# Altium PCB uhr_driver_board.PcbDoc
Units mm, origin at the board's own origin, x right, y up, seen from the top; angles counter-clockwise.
Board outline 152.4 x 101.6 mm, 2 copper layers (Top Layer, Bottom Layer); 130 components, 204 nets, 564 pads, 16 vias.
Unrouted connection lines stored in the file: 255.
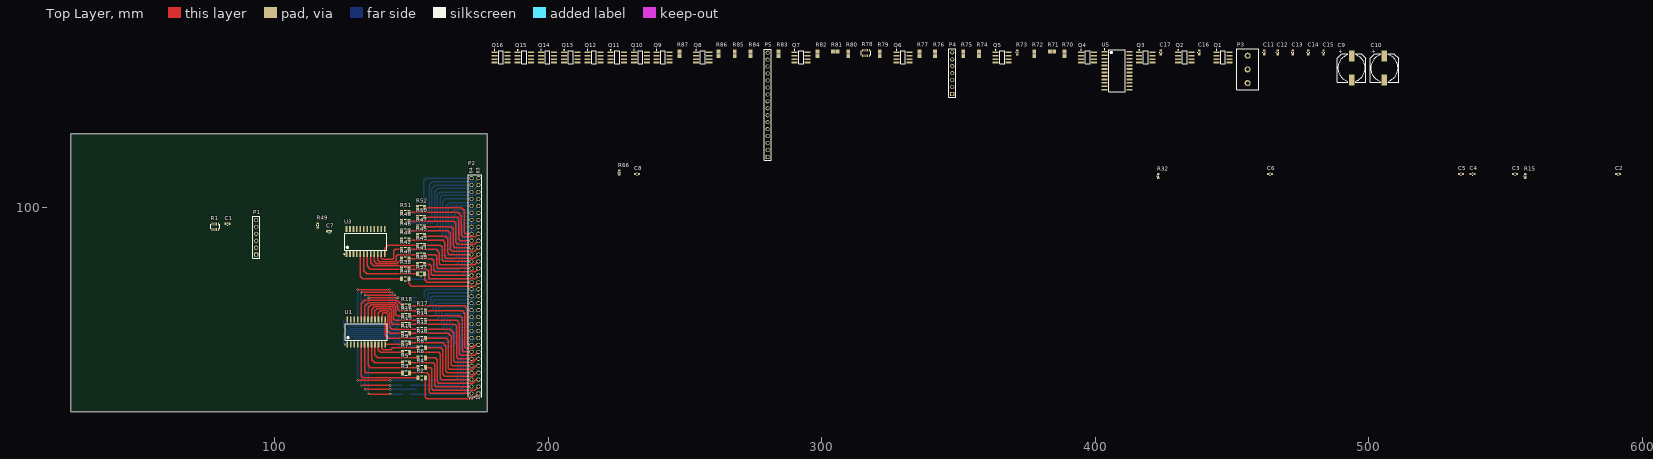
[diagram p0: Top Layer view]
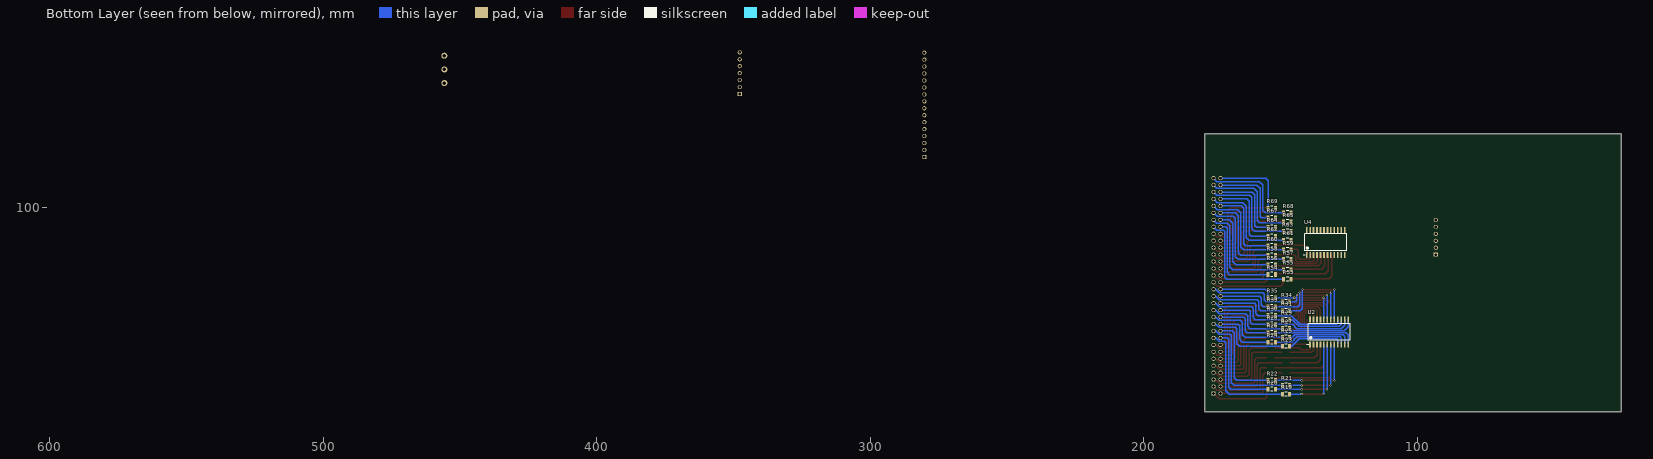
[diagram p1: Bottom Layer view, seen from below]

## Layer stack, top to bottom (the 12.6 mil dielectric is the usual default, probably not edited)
Top Layer: signal copper 0.0356
Dielectric: dielectric 0.32, FR-4, Dk 4.8
Bottom Layer: signal copper 0.0356

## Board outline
25.4,25.4 177.8,25.4 177.8,127 25.4,127

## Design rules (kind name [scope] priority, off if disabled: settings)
Clearance [All] p1: gap=0.125
DiffPairsRouting [All] p1: maxlimit=10 minlimit=0.125 mostfreqgap=0.15 maxuncoupledlength=12.7
FabricationTestPointUsage FabricationTestPointUsage_1 [All] p1: valid=0 allowmultiple=FALSE
FabricationTestpoint FabricationTestpoint_1 [All] p1: side=3 testpointundercomponent=TRUE minsize=1.016 maxsize=2.54 preferedsize=1.524 minholesize=0 maxholesize=1.016 preferedholesize=0.813 testpointgrid=0.025 allowsidetop=TRUE allowsidebottom=TRUE usegrid=TRUE gridtolerance=0
HoleSize [All] p1: absolutevalues=TRUE maxlimit=6 minlimit=0.2 maxpercent=80.000 minpercent=20.000
HoleSize FabricationTestpoint [All] p2 off: absolutevalues=TRUE maxlimit=2.54 minlimit=0.025 maxpercent=80.000 minpercent=20.000
HoleSize FabricationTestPointUsage [All] p3 off: absolutevalues=TRUE maxlimit=2.54 minlimit=0.025 maxpercent=80.000 minpercent=20.000
PlaneClearance [All] p1: clearance=0.5
PlaneConnect [All] p1: planeconnectstyle=Relief reliefexpansion=0.4 reliefentries=4 reliefconductorwidth=0.15 reliefairgap=0.15
PolygonConnect [All] p1: connectstyle=Relief reliefconductorwidth=0.15 reliefentries=4 polygonreliefangle="90 Angle" airgapwidth=0.254
RoutingCorners [All] p1: cornerstyle=45-Degree minsetback=1.25 maxsetback=1.25
RoutingVias [All] p1: holewidth=0.3 width=0.6 viastyle="Through Hole" minholewidth=0.2 minwidth=0.45 maxholewidth=0.45 maxwidth=0.75
SolderMaskExpansion [All] p1: expansion=0.075
Width [All] p1: maxlimit=10 minlimit=0.125 preferedwidth=0.15
21 further rules are at their usual default settings.

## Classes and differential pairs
component class main_driver_column: C1 C2 C3 C4 C5 C6 C7 C8 P1 P2 R1 R2 R3 R4 R5 R6 R7 R8 R9 R10 R11 R12 R13 R14 R15 R16 R17 R19 R20 R21 R22 R23 R24 R25 R26 R27 R28 R29 R30 R31 R32 R33 R34 R35 R36 R37 R38 R39 R40 R41 R42 R43 R44 R45 R46 R47 R48 R49 R50 R51 R52 R53 R54 R55 R56 R57 R58 R59 R60 R61 R62 R63 R64 R65 R66 R67 R68 R69 U1 U2 U3 U4
component class main_driver_row: C9 C10 C11 C12 C13 C14 C15 C16 C17 P3 P4 P5 Q1 Q2 Q3 Q4 Q5 Q6 Q7 Q8 Q9 Q10 Q11 Q12 Q13 Q14 Q15 Q16 R70 R71 R72 R73 R74 R75 R76 R77 R78 R79 R80 R81 R82 R83 R84 R85 R86 R87 U5
net class LED_COL[1..64]: LED_COL1 LED_COL2 LED_COL3 LED_COL4 LED_COL5 LED_COL6 LED_COL7 LED_COL8 LED_COL9 LED_COL10 LED_COL11 LED_COL12 LED_COL13 LED_COL14 LED_COL15 LED_COL16 LED_COL17 LED_COL18 LED_COL19 LED_COL20 LED_COL21 LED_COL22 LED_COL23 LED_COL24 LED_COL25 LED_COL26 LED_COL27 LED_COL28 LED_COL29 LED_COL30 LED_COL31 LED_COL32 LED_COL33 LED_COL34 LED_COL35 LED_COL36 LED_COL37 LED_COL38 LED_COL39 LED_COL40 LED_COL41 LED_COL42 LED_COL43 LED_COL44 LED_COL45 LED_COL46 LED_COL47 LED_COL48 LED_COL49 LED_COL50 LED_COL51 LED_COL52 LED_COL53 LED_COL54 LED_COL55 LED_COL56 LED_COL57 LED_COL58 LED_COL59 LED_COL60 LED_COL61 LED_COL62 LED_COL63 LED_COL64

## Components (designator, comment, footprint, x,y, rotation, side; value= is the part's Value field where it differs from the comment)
C1 "2U2F_0603" C0603 82.749,94 r0 top
C2 "10PF_0603" C0603 591.249,112.25 r0 top
C3 "10PF_0603" C0603 553.499,112.25 r0 top
C4 "10PF_0603" C0603 537.999,112.25 r0 top
C5 "10PF_0603" C0603 533.749,112.25 r0 top
C6 "2U2F_0603" C0603 463.999,112.25 r0 top
C7 "2U2F_0603" C0603 119.95,91.25 r0 top
C8 "2U2F_0603" C0603 232.5,112.25 r0 top
C9 "470UF_V_CAPEIA_G" CAPAE_G 493.749,151 r0 top
C10 "470UF_V_CAPEIA_G" CAPAE_G 505.749,151 r0 top
C11 "2U2F_0603" C0603 461.749,156.75 r90 top
C12 "2U2F_0603" C0603 466.749,156.75 r90 top
C13 "2U2F_0603" C0603 472.249,156.75 r90 top
C14 "2U2F_0603" C0603 477.999,156.75 r90 top
C15 "2U2F_0603" C0603 483.499,156.75 r90 top
C16 "2U2F_0603" C0603 437.999,156.75 r90 top
C17 "100NF_0603" C0603 423.999,156.75 r90 top
P1 "Header 6" HDR1X6_1MM 93.25,82.75 r90 top
P2 "Header 32X2" HDR2X32_1MM 174.5,32 r90 top
P3 "Header 3" Header_3_Screw_5mm 455.749,150.5 r90 top
P4 "Header 7" HDR1X7_1MM 347.749,141.5 r90 top
P5 "Header 16" HDR1X16_1MM 280.249,118.5 r90 top
Q1 "NTMS10P02" SOIC-8 446.749,153 r0 top
Q2 "NTMS10P02" SOIC-8 432.749,153 r0 top
Q3 "NTMS10P02" SOIC-8 418.499,153 r0 top
Q4 "NTMS10P02" SOIC-8 397.249,153 r0 top
Q5 "NTMS10P02" SOIC-8 365.999,153 r0 top
Q6 "NTMS10P02" SOIC-8 329.749,153 r0 top
Q7 "NTMS10P02" SOIC-8 292.499,153 r0 top
Q8 "NTMS10P02" SOIC-8 256.499,153 r0 top
Q9 "NTMS10P02" SOIC-8 242,153 r0 top
Q10 "NTMS10P02" SOIC-8 233.75,153 r0 top
Q11 "NTMS10P02" SOIC-8 225.25,153 r0 top
Q12 "NTMS10P02" SOIC-8 216.75,153 r0 top
Q13 "NTMS10P02" SOIC-8 208.25,153 r0 top
Q14 "NTMS10P02" SOIC-8 199.75,153 r0 top
Q15 "NTMS10P02" SOIC-8 191.25,153 r0 top
Q16 "NTMS10P02" SOIC-8 182.75,153 r0 top
R1 "Res_Array_BCN16" BCN16 78.249,93 r0 top
R2 "15R_1206" R1206 153.75,37.75 r0 top
R3 "15R_1206" R1206 148,39.5 r0 top
R4 "15R_1206" R1206 153.75,41.5 r0 top
R5 "15R_1206" R1206 148,43.25 r0 top
R6 "15R_1206" R1206 153.75,45 r0 top
R7 "15R_1206" R1206 148,47 r0 top
R8 "15R_1206" R1206 153.75,48.75 r0 top
R9 "15R_1206" R1206 148,50.5 r0 top
R10 "15R_1206" R1206 153.75,52.25 r0 top
R11 "15R_1206" R1206 148,54 r0 top
R12 "15R_1206" R1206 153.75,55.5 r0 top
R13 "15R_1206" R1206 148,57.25 r0 top
R14 "15R_1206" R1206 153.75,58.75 r0 top
R15 "680R_0603" R0603 557.249,111.5 r90 top
R16 "15R_1206" R1206 148,60.5 r0 top
R17 "15R_1206" R1206 153.75,62.25 r0 top
R18 "15R_1206" R1206 148,64 r0 top
R19 "15R_1206" R1206 148,31.75 r0 bottom
R20 "15R_1206" R1206 153.25,33.5 r0 bottom
R21 "15R_1206" R1206 148,35 r0 bottom
R22 "15R_1206" R1206 153.25,36.75 r0 bottom
R23 "15R_1206" R1206 148,49.25 r0 bottom
R24 "15R_1206" R1206 153.25,50.75 r0 bottom
R25 "15R_1206" R1206 148,52.5 r0 bottom
R26 "15R_1206" R1206 153.25,54.25 r0 bottom
R27 "15R_1206" R1206 148,55.75 r0 bottom
R28 "15R_1206" R1206 153.25,57.25 r0 bottom
R29 "15R_1206" R1206 148,59 r0 bottom
R30 "15R_1206" R1206 153.25,60.5 r0 bottom
R31 "15R_1206" R1206 148,62.25 r0 bottom
R32 "680R_0603" R0603 422.999,111.5 r90 top
R33 "15R_1206" R1206 153.25,63.75 r0 bottom
R34 "15R_1206" R1206 148,65.5 r0 bottom
R35 "15R_1206" R1206 153.25,67 r0 bottom
R36 "15R_1206" R1206 147.75,74 r0 top
R37 "15R_1206" R1206 153.5,75.75 r0 top
R38 "15R_1206" R1206 147.75,77.5 r0 top
R39 "15R_1206" R1206 153.5,79.25 r0 top
R40 "15R_1206" R1206 147.75,81.25 r0 top
R41 "15R_1206" R1206 153.5,82.75 r0 top
R42 "15R_1206" R1206 147.75,84.75 r0 top
R43 "15R_1206" R1206 153.5,86.25 r0 top
R44 "15R_1206" R1206 147.75,88.25 r0 top
R45 "15R_1206" R1206 153.5,89.75 r0 top
R46 "15R_1206" R1206 147.75,91.5 r0 top
R47 "15R_1206" R1206 153.5,93 r0 top
R48 "15R_1206" R1206 147.75,95 r0 top
R49 "680R_0603" R0603 115.699,93.5 r90 top
R50 "15R_1206" R1206 153.5,96.5 r0 top
R51 "15R_1206" R1206 147.75,98.25 r0 top
R52 "15R_1206" R1206 153.5,100 r0 top
R53 "15R_1206" R1206 147.5,73.75 r0 bottom
R54 "15R_1206" R1206 153.25,75.5 r0 bottom
R55 "15R_1206" R1206 147.5,77.25 r0 bottom
R56 "15R_1206" R1206 153.25,79 r0 bottom
R57 "15R_1206" R1206 147.5,81 r0 bottom
R58 "15R_1206" R1206 153.25,82.5 r0 bottom
R59 "15R_1206" R1206 147.5,84.5 r0 bottom
R60 "15R_1206" R1206 153.25,86 r0 bottom
R61 "15R_1206" R1206 147.5,88 r0 bottom
R62 "15R_1206" R1206 153.25,89.5 r0 bottom
R63 "15R_1206" R1206 147.5,91.25 r0 bottom
R64 "15R_1206" R1206 153.25,92.75 r0 bottom
R65 "15R_1206" R1206 147.5,94.75 r0 bottom
R66 "680R_0603" R0603 226,112.75 r90 top
R67 "15R_1206" R1206 153.25,96.25 r0 bottom
R68 "15R_1206" R1206 147.5,98 r0 bottom
R69 "15R_1206" R1206 153.25,99.75 r0 bottom
R70 "2R2_0805" R0805 388.749,156.25 r90 top
R71 "2R2_0805" R0805 384.249,157 r0 top
R72 "2R2_0805" R0805 377.749,156.25 r90 top
R73 "100R_0603" R0603 371.499,156.75 r90 top
R74 "2R2_0805" R0805 357.499,156.25 r90 top
R75 "2R2_0805" R0805 351.749,156.25 r90 top
R76 "2R2_0805" R0805 341.499,156.25 r90 top
R77 "2R2_0805" R0805 335.749,156.25 r90 top
R78 "Res_Array_BCN16" BCN16 316.249,156.5 r0 top
R79 "2R2_0805" R0805 321.249,156.25 r90 top
R80 "2R2_0805" R0805 309.749,156.25 r90 top
R81 "2R2_0805" R0805 304.999,157 r0 top
R82 "2R2_0805" R0805 298.499,156.25 r90 top
R83 "2R2_0805" R0805 284.249,156.25 r90 top
R84 "2R2_0805" R0805 273.999,156.25 r90 top
R85 "2R2_0805" R0805 268.249,156.25 r90 top
R86 "2R2_0805" R0805 262.249,156.25 r90 top
R87 "2R2_0805" R0805 248,156.25 r90 top
U1 "CAT4016" SOIC-24_W 133.5,54.5 r90 top
U2 "CAT4016" SOIC-24_W 132.25,54.5 r90 bottom
U3 "CAT4016" SOIC-24_W 133.25,87.5 r90 top
U4 "CAT4016" SOIC-24_W 133.5,87.25 r90 bottom
U5 "74HC154" SOIC-24_W 407.999,150 r0 top

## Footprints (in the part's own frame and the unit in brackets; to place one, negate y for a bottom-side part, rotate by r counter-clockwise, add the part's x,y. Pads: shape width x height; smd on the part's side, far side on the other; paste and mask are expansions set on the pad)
BCN16 [mm]
  rect 0.45x1 smd: 1(-1.2,-1) 2(-0.4,-1) 3(0.4,-1) 4(1.2,-1) 5(1.2,1) 6(0.4,1) 7(-0.4,1) 8(-1.2,1)
  silkscreen extent -1.7,-0.8 1.7,0.8, body extent -1.6,-0.8 1.6,0.8, height 0.5
C0603 [mm] "Chip Capacitor, Body 1.6x0.8mm, IPC High Density"
  rect 0.8x0.9 smd: 1(-0.7,0) 2(0.7,0)
  silkscreen extent -0.1,-0.45 0.1,0.45, body extent -0.8,-0.4 0.8,0.4, height 0.55
CAPAE_G [mm]
  rect 2x4.1 smd: 1(0,4.35) 2(0,-4.35)
  silkscreen extent -5.2,-5.2 5.2,5.2, body extent -5.15,-5.8 5.15,5.8, height 10.2
HDR1X6_1MM [mm] "Connector; Header; 6 Position"
  rect 1.5x1.5 hole 1: 1(0,0)
  round 1.5 hole 1: 2(2.54,0) 3(5.08,0) 4(7.62,0) 5(10.16,0) 6(12.7,0)
  silkscreen extent -1.27,-1.27 13.97,1.27
HDR1X7_1MM [mm] "Connector; Header; 7 Position"
  rect 1.5x1.5 hole 1: 1(0,0)
  round 1.5 hole 1: 2(2.54,0) 3(5.08,0) 4(7.62,0) 5(10.16,0) 6(12.7,0) 7(15.24,0)
  silkscreen extent -1.27,-1.27 16.51,1.27
HDR1X16_1MM [mm] "Connector; Header; 16 Position"
  rect 1.5x1.5 hole 1: 1(0,0)
  round 1.5 hole 1: 2(2.54,0) 3(5.08,0) 4(7.62,0) 5(10.16,0) 6(12.7,0) 7(15.24,0) 8(17.78,0) 9(20.32,0) 10(22.86,0) 11(25.4,0) 12(27.94,0) 13(30.48,0) 14(33.02,0) 15(35.56,0) 16(38.1,0)
  silkscreen extent -1.27,-1.27 39.37,1.27
HDR2X32_1MM [mm] "Connector; Header; 30x2 Position"
  rect 1.5x1.5 hole 1: 1(0,0)
  round 1.5 hole 1: 2(0,2.54) 3(2.54,0) 4(2.54,2.54) 5(5.08,0) 6(5.08,2.54) 7(7.62,0) 8(7.62,2.54) 9(10.16,0) 10(10.16,2.54) 11(12.7,0) 12(12.7,2.54) 13(15.24,0) 14(15.24,2.54) 15(17.78,0) 16(17.78,2.54) 17(20.32,0) 18(20.32,2.54) 19(22.86,0) 20(22.86,2.54) 21(25.4,0) 22(25.4,2.54) 23(27.94,0) 24(27.94,2.54) 25(30.48,0) 26(30.48,2.54) 27(33.02,0) 28(33.02,2.54) 29(35.56,0) 30(35.56,2.54) 31(38.1,0) 32(38.1,2.54) 33(40.64,0) 34(40.64,2.54) 35(43.18,0) 36(43.18,2.54) 37(45.72,0) 38(45.72,2.54) 39(48.26,0) 40(48.26,2.54) 41(50.8,0) 42(50.8,2.54) 43(53.34,0) 44(53.34,2.54) 45(55.88,0) 46(55.88,2.54) 47(58.42,0) 48(58.42,2.54) 49(60.96,0) 50(60.96,2.54) 51(63.5,0) 52(63.5,2.54) 53(66.04,0) 54(66.04,2.54) 55(68.58,0) 56(68.58,2.54) 57(71.12,0) 58(71.12,2.54) 59(73.66,0) 60(73.66,2.54) 61(76.2,0) 62(76.2,2.54) 63(78.74,0) 64(78.74,2.54)
  silkscreen extent -1.27,-1.27 79.9,3.81
Header_3_Screw_5mm [mm]
  round 2.2 hole 1.3: 1(-5,0) 2(0,0) 3(5,0)
  silkscreen extent -7.5,-4 7.5,4
R0603 [mm]
  rect 0.7x0.9 smd: 1(-0.751,0.008) 2(0.749,0.008)
  silkscreen extent -0.2,-0.34 0.2,0.36, body extent -0.8,-0.39 0.8,0.41, height 0.5
R0805 [mm] "Chip Resistor, Body 2.0x1.2mm, IPC Medium Density"
  rect 1.2x1.4 smd: 1(-0.9,0) 2(0.9,0)
  silkscreen extent 0,-0.6 0,0.6, body extent -1,-0.6 1,0.6, height 0.5
R1206 [mm] "Chip Resistor, Body 3.2x1.6mm, IPC High Density"
  rect 1.1x1.7 smd: 1(-1.35,0) 2(1.35,0)
  silkscreen extent -0.4,-0.75 0.4,0.75, body extent -1.6,-0.8 1.6,0.8, height 0.6
SOIC-8 [mm] "8-Pin Small Outline Integrated Circuit 1.27 mm Pitch, IPC Medium Density"
  rect 2.2x0.6 smd: 1(-2.4,3.81) 2(-2.4,2.54) 3(-2.4,1.27) 4(-2.4,0) 5(2.4,0) 6(2.4,1.27) 7(2.4,2.54) 8(2.4,3.81)
  silkscreen extent -2.52,-0.48 0.9,4.78, body extent -3,-0.52 3,4.38, height 1.63
SOIC-24_W [mm] "SOIC, 24-Leads, Body 15,30x7,47mm, Pitch 1,27mm, IPC Medium Density"
  rect 2.2x0.6 smd: 1(-4.575,6.985) 2(-4.575,5.715) 3(-4.575,4.445) 4(-4.575,3.175) 5(-4.575,1.905) 6(-4.575,0.635) 7(-4.575,-0.635) 8(-4.575,-1.905) 9(-4.575,-3.175) 10(-4.575,-4.445) 11(-4.575,-5.715) 12(-4.575,-6.985) 13(4.575,-6.985) 14(4.575,-5.715) 15(4.575,-4.445) 16(4.575,-3.175) 17(4.575,-1.905) 18(4.575,-0.635) 19(4.575,0.635) 20(4.575,1.905) 21(4.575,3.175) 22(4.575,4.445) 23(4.575,5.715) 24(4.575,6.985)
  silkscreen extent -4.7,-7.7 3.08,7.96, body extent -5.15,-7.75 5.15,7.75, height 2.65

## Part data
C1 C2 C3 C4 C5 C6 C7 C8 C11 C12 C13 C14 C15 C16 C17: library part "Cap Semi", "Capacitor (Semiconductor SIM Model)"
C9 C10: library part "Cap Pol1", "Polarized Capacitor (Radial)"
P1: "Header, 6-Pin"
P2: "Header, 32-Pin, Dual row"
P3: "Header, 3-Pin"
P4: "Header, 7-Pin"
P5: "Header, 16-Pin"
Q1 Q2 Q3 Q4 Q5 Q6 Q7 Q8 Q9 Q10 Q11 Q12 Q13 Q14 Q15 Q16: "P-Channel MOSFET SO8"
R1 R78: "Resistor"
R2 R3 R4 R5 R6 R7 R8 R9 R10 R11 R12 R13 R14 R15 R16 R17 R18 R19 R20 R21 R22 R23 R24 R25 R26 R27 R28 R29 R30 R31 R32 R33 R34 R35 R36 R37 R38 R39 R40 R41 R42 R43 R44 R45 R46 R47 R48 R49 R50 R51 R52 R53 R54 R55 R56 R57 R58 R59 R60 R61 R62 R63 R64 R65 R66 R67 R68 R69 R70 R71 R72 R73 R74 R75 R76 R77 R79 R80 R81 R82 R83 R84 R85 R86 R87: library part Res3, "Resistor"
U1 U2 U3 U4: "16channel LED driver - constant current"

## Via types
v1: diameter 0.75, hole 0.45, Top Layer to Bottom Layer, 16 vias

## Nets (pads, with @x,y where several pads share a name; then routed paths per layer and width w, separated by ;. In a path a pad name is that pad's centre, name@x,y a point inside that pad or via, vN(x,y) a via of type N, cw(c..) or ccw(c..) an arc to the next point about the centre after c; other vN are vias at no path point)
COL_BLANK: C5.2 R1.5 U1.21 U2.21 U3.21 U4.21
COL_CLK: C2.2 R1.8 U1.3 U2.3 U3.3 U4.3
COL_LATCH: C4.2 R1.6 U1.4 U2.4 U3.4 U4.4
COL_SIN: C3.2 R1.7 U1.2
GND: C1.1 C2.1 C3.1 C4.1 C5.1 C6.1 C7.1 C8.1 C9.2 C10.2 C11.1 C12.1 C13.1 C14.1 C15.1 C16.1 C17.1 P1.1 P3.3 P4.7 R15.2 R32.2 R49.2 R66.2 U1.1 U2.1 U3.1 U4.1 U5.12 U5.19
LED1: P2.1 R2.2 | length 27.6
  Top Layer w0.5: R2.2 155.1,30.65 155.75,30 172.5,30 P2.1
LED2: P2.2 R3.2 | length 28.9
  Top Layer w0.5: R3.2 155.75,39.5 156.5,38.75 156.5,32.5 157,32 P2.2@171.46,32
LED3: P2.3 R4.2 | length 27.6
  Top Layer w0.5: R4.2 157,41.5 157.5,41 157.5,33.75 158,33.25 171.437,33.25 171.441,33.254 173.214,33.254 P2.3
LED4: P2.4 R5.2 | length 30.3
  Top Layer w0.5: R5.2 158,43.25 158.5,42.75 158.5,35 158.96,34.54 P2.4@171.46,34.54
LED5: P2.5 R6.2 | length 28.4
  Top Layer w0.5: R6.2 158.75,45 159.5,44.25 159.5,36.25 159.924,35.826 172.479,35.826 173.733,37.08 P2.5
LED6: P2.6 R7.2 | length 31.3
  Top Layer w0.5: R7.2 160,47 160.5,46.5 160.5,37.75 161.17,37.08 P2.6@171.46,37.08
LED7: P2.7 R8.2 | length 29.5
  Top Layer w0.5: R8.2 160.75,48.75 161.5,48 161.5,38.982 162.116,38.366 172.479,38.366 173.733,39.62 P2.7
LED8: P2.8 R9.2 | length 32
  Top Layer w0.5: R9.2 161.5,50.5 162.5,49.5 162.5,40.25 163.13,39.62 P2.8@171.46,39.62
LED9: P2.9 R10.2 | length 30.6
  Top Layer w0.5: R10.2 162.75,52.25 163.5,51.5 163.5,41.312 163.906,40.906 172.479,40.906 173.733,42.16 P2.9
LED10: P2.10 R11.2 | length 33.2
  Top Layer w0.5: R11.2 163.5,54 164.5,53 164.5,42.5 164.84,42.16 P2.10@171.46,42.16
LED11: P2.11 R12.2 | length 30.9
  Top Layer w0.5: R12.2 164.25,55.5 165.5,54.25 165.5,44 166.054,43.446 172.479,43.446 173.733,44.7 P2.11
LED12: P2.12 R13.2 | length 33.9
  Top Layer w0.5: R13.2 165.75,57.25 166.5,56.5 166.5,45.25 167.05,44.7 P2.12@171.46,44.7
LED13: P2.13 R14.2 | length 31.8
  Top Layer w0.5: R14.2 166.5,58.75 167.5,57.75 167.5,46.5 168,46 171.441,46 ; 171.427,46 171.441,45.986 173.246,45.986 P2.13
LED14: P2.14 R16.2 | length 34.6
  Top Layer w0.5: R16.2 167.75,60.5 168.5,59.75 168.5,47.75 169.01,47.24 P2.14@171.46,47.24
LED15: P2.15 R17.2 | length 32.9
  Top Layer w0.5: R17.2 168.5,62.25 169.5,61.25 169.5,48.802 169.776,48.526 172.479,48.526 173.733,49.78 P2.15
LED16: P2.16 R18.2 | length 35.9
  Top Layer w0.5: R18.2 169.5,64 170.5,63 170.5,50.31 171.03,49.78 P2.16
LED17: P2.17 R19.2 | length 43.9
  Bottom Layer w0.5: R19.2 168.75,31.75 170,33 170,50.5 170.566,51.066 172.479,51.066 173.733,52.32 P2.17
LED18: P2.18 R20.2 | length 35.4
  Bottom Layer w0.5: R20.2 168.25,33.5 169,34.25 169,51.75 169.57,52.32 P2.18
LED19: P2.19 R21.2 | length 43.5
  Bottom Layer w0.5: R21.2 167,35 168,36 168,53.246 168.36,53.606 172.479,53.606 173.733,54.86 P2.19
LED20: P2.20 R22.2 | length 34.5
  Bottom Layer w0.5: R22.2 166,36.75 167,37.75 167,54.25 167.61,54.86 P2.20
LED21: P2.21 R23.2 | length 31.7
  Bottom Layer w0.5: R23.2 165,49.25 166,50.25 166,55.75 166.396,56.146 172.479,56.146 173.733,57.4 P2.21
LED22: P2.22 R24.2 | length 23
  Bottom Layer w0.5: R24.2 164,50.75 165,51.75 165,56.75 165.65,57.4 P2.22
LED23: P2.23 R25.2 | length 30.9
  Bottom Layer w0.5: R25.2 163,52.5 164,53.5 164,58 164.686,58.686 172.479,58.686 173.733,59.94 P2.23
LED24: P2.24 R26.2 | length 22.4
  Bottom Layer w0.5: R26.2 162.25,54.25 163,55 163,59.5 163.44,59.94 P2.24
LED25: P2.25 R27.2 | length 30.3
  Bottom Layer w0.5: R27.2 161.25,55.75 162,56.5 162,60.5 162.726,61.226 172.479,61.226 173.733,62.48 P2.25
LED26: P2.26 R28.2 | length 21.9
  Bottom Layer w0.5: R28.2 160.25,57.25 161,58 161,62 161.48,62.48 P2.26
LED27: P2.27 R29.2 | length 29.7
  Bottom Layer w0.5: R29.2 159.25,59 160,59.75 160,63.25 160.516,63.766 172.479,63.766 173.733,65.02 P2.27
LED28: P2.28 R30.2 | length 21.1
  Bottom Layer w0.5: R30.2 158.25,60.5 159,61.25 159,64.5 159.52,65.02 P2.28
LED29: P2.29 R31.2 | length 29
  Bottom Layer w0.5: R31.2 157.25,62.25 158,63 158,65.75 158.556,66.306 172.479,66.306 173.733,67.56 P2.29
LED30: P2.30 R33.2 | length 20.4
  Bottom Layer w0.5: R33.2 156.25,63.75 157,64.5 157,67 157.56,67.56 P2.30
LED31: P2.31 R34.2 | length 28.2
  Bottom Layer w0.5: R34.2 155.25,65.5 156,66.25 156,68.25 156.596,68.846 172.479,68.846 173.733,70.1 P2.31
LED32: P2.32 R35.2 | length 19.9
  Bottom Layer w0.5: R35.2 154.75,67.15 154.75,69.25 155.6,70.1 P2.32
LED33: P2.33 R36.2 | length 28.3
  Top Layer w0.5: R36.2 149,73.9 149,72.25 150,71.25 173.11,71.25 P2.33
LED34: P2.34 R37.2 | length 19.6
  Top Layer w0.5: R37.2 154.85,73.65 155.86,72.64 P2.34
LED35: P2.35 R38.2 | length 28.7
  Top Layer w0.5: R38.2 155.5,77.5 156.25,76.75 156.25,74.5 156.75,74 173.32,74 P2.35
LED36: P2.36 R39.2 | length 20.4
  Top Layer w0.5: R39.2 156.5,79.25 157.25,78.5 157.25,75.75 157.82,75.18 P2.36
LED37: P2.37 R40.2 | length 29.9
  Top Layer w0.5: R40.2 157.5,81.25 158.25,80.5 158.25,77 158.75,76.5 173.28,76.5 P2.37
LED38: P2.38 R41.2 | length 21.5
  Top Layer w0.5: R41.2 158.75,82.75 159.25,82.25 159.25,78.25 159.78,77.72 P2.38
LED39: P2.39 R42.2 | length 30.6
  Top Layer w0.5: R42.2 159,84.75 160.25,83.5 160.25,79.5 160.75,79 173.24,79 P2.39
LED40: P2.40 R43.2 | length 22.4
  Top Layer w0.5: R43.2 160.5,86.25 161.25,85.5 161.25,80.75 161.74,80.26 P2.40
LED41: P2.41 R44.2 | length 31.8
  Top Layer w0.5: R44.2 149.35,88 161.5,88 162.25,87.25 162.25,82 162.75,81.5 173.2,81.5 P2.41
LED42: P2.42 R45.2 | length 23.1
  Top Layer w0.5: R45.2 155.1,89.5 162.5,89.5 163.25,88.75 163.25,83.5 163.95,82.8 P2.42
LED43: P2.43 R46.2 | length 32.4
  Top Layer w0.5: R46.2 163.25,91.5 164.25,90.5 164.25,84.75 165,84 173.16,84 P2.43
LED44: P2.44 R47.2 | length 23.9
  Top Layer w0.5: R47.2 164.5,93 165.25,92.25 165.25,86 165.91,85.34 P2.44
LED45: P2.45 R48.2 | length 33.7
  Top Layer w0.5: R48.2 165.75,95 166.25,94.5 166.25,87.25 167,86.5 173.12,86.5 P2.45
LED46: P2.46 R50.2 | length 25.1
  Top Layer w0.5: R50.2 166.75,96.5 167.25,96 167.25,88.5 167.87,87.88 P2.46
LED47: P2.47 R51.2 | length 33.7
  Top Layer w0.5: R51.2 167,98.25 168.25,97 168.25,90 169,89.25 173.33,89.25 P2.47
LED48: P2.48 R52.2 | length 25.8
  Top Layer w0.5: R52.2 168.25,100 169.25,99 169.25,91 169.83,90.42 P2.48
LED49: P2.49 R53.2 | length 43.4
  Bottom Layer w0.5: R53.2 169.75,73.75 170.5,74.5 170.5,91.25 171,91.75 173.29,91.75 P2.49
LED50: P2.50 R54.2 | length 34.1
  Bottom Layer w0.5: R54.2 168.75,75.5 169.5,76.25 169.5,92.5 169.96,92.96 P2.50
LED51: P2.51 R55.2 | length 42
  Bottom Layer w0.5: R55.2 167.5,77.25 168.5,78.25 168.5,93.25 169.5,94.25 173.25,94.25 P2.51
LED52: P2.52 R56.2 | length 32.4
  Bottom Layer w0.5: R56.2 166.25,79 167.5,80.25 167.5,94.25 168.75,95.5 P2.52
LED53: P2.53 R57.2 | length 40.9
  Bottom Layer w0.5: R57.2 165.5,81 166.5,82 166.5,96 167.25,96.75 173.21,96.75 P2.53
LED54: P2.54 R58.2 | length 31.7
  Bottom Layer w0.5: R58.2 164.5,82.5 165.5,83.5 165.5,97 166.54,98.04 P2.54
LED55: P2.55 R59.2 | length 39.6
  Bottom Layer w0.5: R59.2 163.5,84.5 164.5,85.5 164.5,98 165.75,99.25 173.17,99.25 P2.55
LED56: P2.56 R60.2 | length 31
  Bottom Layer w0.5: R60.2 162.75,86 163.5,86.75 163.5,99.75 164.33,100.58 P2.56
LED57: P2.57 R61.2 | length 38.6
  Bottom Layer w0.5: R61.2 161.5,88 162.5,89 162.5,100.5 163.75,101.75 173.13,101.75 P2.57
LED58: P2.58 R62.2 | length 30
  Bottom Layer w0.5: R62.2 160.75,89.5 161.5,90.25 161.5,102.25 162.37,103.12 P2.58
LED59: P2.59 R63.2 | length 38.4
  Bottom Layer w0.5: R63.2 159.5,91.25 160.5,92.25 160.5,103.75 161.25,104.5 173.34,104.5 P2.59
LED60: P2.60 R64.2 | length 29.3
  Bottom Layer w0.5: R64.2 158.75,92.75 159.5,93.5 159.5,104.75 160.41,105.66 P2.60
LED61: P2.61 R65.2 | length 37.6
  Bottom Layer w0.5: R65.2 149.1,94.5 157.75,94.5 158.5,95.25 158.5,105.75 159.75,107 173.3,107 P2.61
LED62: P2.62 R67.2 | length 28.3
  Bottom Layer w0.5: R67.2 157,96.25 157.5,96.75 157.5,107 158.7,108.2 P2.62
LED63: P2.63 R68.2 | length 36.3
  Bottom Layer w0.5: R68.2 155.5,98 156.5,99 156.5,108.25 157.75,109.5 173.26,109.5 P2.63
LED64: P2.64 R69.2 | length 27.9
  Bottom Layer w0.5: R69.2 154.5,99.85 154.5,109.75 155.49,110.74 P2.64
NetP1_2: P1.2 R1.4
NetP1_3: P1.3 R1.3
NetP1_4: P1.4 R1.2
NetP1_5: P1.5 R1.1
NetP4_2: P4.2 R73.1
NetP4_3: P4.3 R78.1
NetP4_4: P4.4 R78.2
NetP4_5: P4.5 R78.3
NetP4_6: P4.6 R78.4
NetP5_1: P5.1 Q1.5 Q1.6 Q1.7 Q1.8
NetP5_2: P5.2 Q2.5 Q2.6 Q2.7 Q2.8
NetP5_3: P5.3 Q3.5 Q3.6 Q3.7 Q3.8
NetP5_4: P5.4 Q4.5 Q4.6 Q4.7 Q4.8
NetP5_5: P5.5 Q5.5 Q5.6 Q5.7 Q5.8
NetP5_6: P5.6 Q6.5 Q6.6 Q6.7 Q6.8
NetP5_7: P5.7 Q7.5 Q7.6 Q7.7 Q7.8
NetP5_8: P5.8 Q8.5 Q8.6 Q8.7 Q8.8
NetP5_9: P5.9 Q9.5 Q9.6 Q9.7 Q9.8
NetP5_10: P5.10 Q10.5 Q10.6 Q10.7 Q10.8
NetP5_11: P5.11 Q11.5 Q11.6 Q11.7 Q11.8
NetP5_12: P5.12 Q12.5 Q12.6 Q12.7 Q12.8
NetP5_13: P5.13 Q13.5 Q13.6 Q13.7 Q13.8
NetP5_14: P5.14 Q14.5 Q14.6 Q14.7 Q14.8
NetP5_15: P5.15 Q15.5 Q15.6 Q15.7 Q15.8
NetP5_16: P5.16 Q16.5 Q16.6 Q16.7 Q16.8
NetQ1_4: Q1.4 R70.2
NetQ2_4: Q2.4 R71.2
NetQ3_4: Q3.4 R72.2
NetQ4_4: Q4.4 R74.2
NetQ5_4: Q5.4 R75.2
NetQ6_4: Q6.4 R76.2
NetQ7_4: Q7.4 R77.2
NetQ8_4: Q8.4 R79.2
NetQ9_4: Q9.4 R80.2
NetQ10_4: Q10.4 R81.2
NetQ11_4: Q11.4 R82.2
NetQ12_4: Q12.4 R83.2
NetQ13_4: Q13.4 R84.2
NetQ14_4: Q14.4 R85.2
NetQ15_4: Q15.4 R86.2
NetQ16_4: Q16.4 R87.2
NetR2_1: R2.1 U1.5 | length 32.6
  Top Layer w0.5: U1.5 131.595,38.405 132.25,37.75 R2.1
NetR3_1: R3.1 U1.6 | length 23.8
  Top Layer w0.5: U1.6 132.865,40.135 133.5,39.5 R3.1
NetR4_1: R4.1 U1.7 | length 26.2
  Top Layer w0.5: U1.7 134.135,42.365 135,41.5 R4.1
NetR5_1: R5.1 U1.8 | length 17.3
  Top Layer w0.5: U1.8 135.405,44.345 136.5,43.25 R5.1
NetR6_1: R6.1 U1.9 | length 20
  Top Layer w0.5: U1.9 136.675,46.075 137.75,45 R6.1
NetR7_1: R7.1 U1.10 | length 11.2
  Top Layer w0.5: U1.10 137.945,47.805 138.75,47 R7.1
NetR8_1: R8.1 U1.11 | length 15.3
  Top Layer w0.5: U1.11 139.215,48.285 139.5,48 142.5,48 143.25,48.75 R8.1
NetR9_1: R9.1 U1.12 | length 6.4
  Top Layer w0.5: U1.12 146.075,49.925 R9.1
NetR10_1: R10.1 U1.13 | length 18.1
  Top Layer w0.5: U1.13 140.485,53.265 141.5,52.25 R10.1
NetR11_1: R11.1 U1.14 | length 16.2
  Top Layer w0.5: U1.14 139.25,59.11 139.25,61 139.718,61.468 140.782,61.468 141.289,60.961 141.289,57.766 141.242,57.719 141.242,55.008 142.25,54 R11.1
NetR12_1: R12.1 U1.15 | length 23
  Top Layer w0.5: U1.15 137.945,61.445 138.738,62.238 141.262,62.238 142.043,61.457 142.043,57.454 142,57.411 142,56.293 142.793,55.5 R12.1
NetR13_1: R13.1 U1.16 | length 18.6
  Top Layer w0.5: U1.16 136.675,62.175 137.492,62.992 142.258,62.992 142.797,62.453 142.797,57.703 143.25,57.25 R13.1
NetR14_1: R14.1 U1.17 | length 25.4
  Top Layer w0.5: U1.17 135.405,62.655 136.496,63.746 143.004,63.746 143.551,63.199 143.551,59.199 144,58.75 R14.1
NetR15_1: R15.1 U1.23
NetR16_1: R16.1 U1.18 | length 20.7
  Top Layer w0.5: U1.18 134.135,63.385 135.25,64.5 143.5,64.5 144.305,63.695 144.305,60.75 144.555,60.5 R16.1
NetR17_1: R17.1 U1.19 | length 26.9
  Top Layer w0.5: U1.19 132.865,63.865 134.25,65.25 134.934,65.25 134.938,65.254 143.996,65.254 145.059,64.191 145.059,62.941 145.75,62.25 R17.1
NetR18_1: R18.1 U1.20 | length 22.1
  Top Layer w0.5: U1.20 131.595,64.845 132.758,66.008 144.642,66.008 R18.1
NetR19_1: R19.1 U2.5 | length 30.6
  Top Layer w0.5: v1(134.25,31.75) v1(142.25,31.75)
  Bottom Layer w0.5: U2.5 134.155,31.845 v1(134.25,31.75) ; v1(142.25,31.75) R19.1
NetR20_1: R20.1 U2.6 | length 35.4
  Top Layer w0.5: v1(133,33.5) v1(142.25,33.5)
  Bottom Layer w0.5: U2.6 132.885,33.615 v1(133,33.5) ; v1(142.25,33.5) R20.1
NetR21_1: R21.1 U2.7 | length 29.9
  Top Layer w0.5: v1(131.73,35) v1(142.25,35)
  Bottom Layer w0.5: U2.7 131.615,35.115 v1(131.73,35) ; v1(142.25,35) R21.1
NetR22_1: R22.1 U2.8 | length 34.9
  Top Layer w0.5: v1(130.25,36.75) v1(142.25,36.75)
  Bottom Layer w0.5: v1(130.25,36.75) 130.345,36.845 U2.8 ; v1(142.25,36.75) R22.1
NetR23_1: R23.1 U2.9 | length 20.6
  Bottom Layer w0.5: U2.9 129.075,51.675 129.376,51.976 143.258,51.976 145.984,49.25 R23.1
NetR24_1: R24.1 U2.10 | length 27.6
  Bottom Layer w0.5: U2.10 127.805,52.445 128.09,52.73 144.02,52.73 146,50.75 R24.1
NetR25_1: R25.1 U2.11 | length 23.8
  Bottom Layer w0.5: U2.11 126.535,52.965 127.058,53.488 127.357,53.488 127.361,53.484 144.499,53.484 144.503,53.488 144.762,53.488 145.75,52.5 R25.1
NetR26_1: R26.1 U2.12 | length 30.5
  Bottom Layer w0.5: U2.12 125.265,53.511 126.004,54.25 126.434,54.25 126.442,54.242 127.669,54.242 127.673,54.238 144.187,54.238 144.191,54.242 151.892,54.242 R26.1
NetR27_1: R27.1 U2.13 | length 24.9
  Bottom Layer w0.5: U2.13 125.265,56.485 126.754,54.996 127.981,54.996 127.985,54.992 143.875,54.992 143.879,54.996 145.896,54.996 R27.1
NetR28_1: R28.1 U2.14 | length 28.6
  Bottom Layer w0.5: U2.14 126.535,57.035 127.82,55.75 128.294,55.75 128.298,55.746 143.562,55.746 143.566,55.75 144,55.75 145.5,57.25 R28.1
NetR29_1: R29.1 U2.15 | length 22
  Bottom Layer w0.5: U2.15 127.805,57.305 128.61,56.5 143.25,56.5 145.75,59 R29.1
NetR30_1: R30.1 U2.16 | length 25.8
  Bottom Layer w0.5: U2.16 129.075,57.575 129.396,57.254 142.791,57.254 146.037,60.5 R30.1
NetR31_1: R31.1 U2.17 | length 34.7
  Top Layer w0.5: v1(130.25,70) v1(142,70)
  Bottom Layer w0.5: v1(130.25,70) 130.345,69.905 U2.17 ; v1(142,70) 142,63 142.75,62.25 R31.1
NetR32_1: R32.1 U2.23
NetR33_1: R33.1 U2.18 | length 35.2
  Top Layer w0.5: v1(131.5,69) v1(143,69)
  Bottom Layer w0.5: v1(131.5,69) 131.615,68.885 U2.18 ; v1(143,69) 143,64.5 143.75,63.75 R33.1
NetR34_1: R34.1 U2.19 | length 24.8
  Top Layer w0.5: v1(133,68) v1(144,68)
  Bottom Layer w0.5: U2.19 132.885,67.885 v1(133,68) ; v1(144,68) 144,66 144.5,65.5 R34.1
NetR35_1: R35.1 U2.20 | length 25.6
  Top Layer w0.5: v1(134.25,67) v1(145,67)
  Bottom Layer w0.5: U2.20 134.155,66.905 v1(134.25,67) ; v1(145,67) R35.1
NetR36_1: R36.1 U3.5 | length 23.4
  Top Layer w0.5: U3.5 131.345,74.905 132.25,74 R36.1
NetR37_1: R37.1 U3.6 | length 26
  Top Layer w0.5: U3.6 132.615,76.885 133.75,75.75 R37.1
NetR38_1: R38.1 U3.7 | length 17.3
  Top Layer w0.5: U3.7 133.885,78.615 135,77.5 R38.1
NetR39_1: R39.1 U3.8 | length 20.7
  Top Layer w0.5: U3.8 135.155,79.845 136.25,78.75 151.65,78.75 R39.1
NetR40_1: R40.1 U3.9 | length 13.6
  Top Layer w0.5: U3.9 136.425,80.325 137.25,79.5 144.65,79.5 R40.1
NetR41_1: R41.1 U3.10 | length 18.7
  Top Layer w0.5: U3.10 137.695,80.805 138.25,80.25 144,80.25 144.5,80.75 144.5,82.25 145,82.75 R41.1
NetR42_1: R42.1 U3.11 | length 12.2
  Top Layer w0.5: U3.11 138.965,81.535 139.5,81 143,81 143.5,81.5 143.5,84.25 144,84.75 R42.1
NetR43_1: R43.1 U3.12 | length 14.5
  Top Layer w0.5: U3.12 140.235,84.985 141.5,86.25 R43.1
NetR44_1: R44.1 U3.13
NetR45_1: R45.1 U3.14
NetR46_1: R46.1 U3.15
NetR47_1: R47.1 U3.16
NetR48_1: R48.1 U3.17
NetR49_1: R49.1 U3.23
NetR50_1: R50.1 U3.18
NetR51_1: R51.1 U3.19
NetR52_1: R52.1 U3.20
NetR53_1: R53.1 U4.5
NetR54_1: R54.1 U4.6
NetR55_1: R55.1 U4.7
NetR56_1: R56.1 U4.8
NetR57_1: R57.1 U4.9
NetR58_1: R58.1 U4.10
NetR59_1: R59.1 U4.11
NetR60_1: R60.1 U4.12
NetR61_1: R61.1 U4.13
NetR62_1: R62.1 U4.14
NetR63_1: R63.1 U4.15
NetR64_1: R64.1 U4.16
NetR65_1: R65.1 U4.17
NetR66_1: R66.1 U4.23
NetR67_1: R67.1 U4.18
NetR68_1: R68.1 U4.19
NetR69_1: R69.1 U4.20
NetR70_1: R70.1 U5.1
NetR71_1: R71.1 U5.2
NetR72_1: R72.1 U5.3
NetR73_2: R73.2 U5.18
NetR74_1: R74.1 U5.4
NetR75_1: R75.1 U5.5
NetR76_1: R76.1 U5.6
NetR77_1: R77.1 U5.7
NetR78_5: R78.5 U5.20
NetR78_6: R78.6 U5.21
NetR78_7: R78.7 U5.22
NetR78_8: R78.8 U5.23
NetR79_1: R79.1 U5.8
NetR80_1: R80.1 U5.9
NetR81_1: R81.1 U5.10
NetR82_1: R82.1 U5.11
NetR83_1: R83.1 U5.13
NetR84_1: R84.1 U5.14
NetR85_1: R85.1 U5.15
NetR86_1: R86.1 U5.16
NetR87_1: R87.1 U5.17
NetU1_22: U1.22 U2.2
NetU2_22: U2.22 U3.2
NetU3_22: U3.22 U4.2
VCC: C1.2 C6.2 C7.2 C8.2 C16.2 C17.2 P1.6 P3.1 P4.1 U1.24 U2.24 U3.24 U4.24 U5.24
VCC_PWR: C9.1 C10.1 C11.2 C12.2 C13.2 C14.2 C15.2 P3.2 Q1.1 Q1.2 Q1.3 Q2.1 Q2.2 Q2.3 Q3.1 Q3.2 Q3.3 Q4.1 Q4.2 Q4.3 Q5.1 Q5.2 Q5.3 Q6.1 Q6.2 Q6.3 Q7.1 Q7.2 Q7.3 Q8.1 Q8.2 Q8.3 Q9.1 Q9.2 Q9.3 Q10.1 Q10.2 Q10.3 Q11.1 Q11.2 Q11.3 Q12.1 Q12.2 Q12.3 Q13.1 Q13.2 Q13.3 Q14.1 Q14.2 Q14.3 Q15.1 Q15.2 Q15.3 Q16.1 Q16.2 Q16.3
pads on no net: U4.22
